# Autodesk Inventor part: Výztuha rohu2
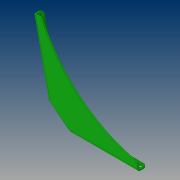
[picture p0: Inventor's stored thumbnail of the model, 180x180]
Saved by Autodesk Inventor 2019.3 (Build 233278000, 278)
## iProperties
Created: 2019-02
Part Number: Výztuha rohu2
Material: Ocel, měkká, svařovaná
Document SubType Name: Plech
Designer: B-hon
Density: 7.85 g/cm^3
Sheet Metal Rule: Výchozí_mm
Appearance: Tmavě zelená
Author: B-hon
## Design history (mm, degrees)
node "Plocha2"
  sketch "Náčrt1"
    geometry: L1 (0, 0)-(-10.396, 48.907); L2 (0, 0)-(50, 0); L3 (-51.978, 244.537)-(-37.306, 247.656); L4 (0, 0)-(226.092, 279.201); L5 (250, 0)-(250, 15); L6 (50, 0)-(50, -8); L7 (50, -8)-(250, -8); L8 (250, -8)-(250, 0); L9 (-10.396, 48.907)-(-18.221, 47.244); L10 (-18.221, 47.244)-(-59.803, 242.874); L11 (-59.803, 242.874)-(-51.978, 244.537); L12 (-51.978, 244.537)-(148.022, 244.537); A1 r 400 centre (329.584, 407.003) between (-37.306, 247.656) and (250, 15)
    constraints: 24 end point, 2 horizontal, 2 parallel, 2 point on circle, 1 centre point, 1 perpendicular, 1 point on line, 1 vertical
    dimensions: "d0" = 250 distance of L1.start L5.start; "d1" = 250 distance of L1.start L3.start; "d2" = 102 deg angle of L2 L1; "d3" = 15 distance of L3.start L3.end; "d5" = 51 deg angle of L2 L4 (= 0.5 x d2); "d6" = 400 radius of A1; "d39" = 200 distance of L7.end L6.end; "d40" = 8 distance of L2.end L6.end; "d41" = 200 distance of L1.end L3.start; "d43" = 8 distance of L1.end L9.end (= d40)
node "Obruba4"
node "Obruba5"
chamfer "Zkosení1" distance "d68" = 45; stored, may be unused: second distance "d69" = 2, angle "d70" = 45 deg
fillet "Zaoblení3" dims "d71" = 10
fillet "Zaoblení4" dims "d72" = 10
fillet "Zaoblení5" dims "d73" = 15
sketch "Náčrt9"
  geometry: A1 r 10 centre (190, 10) between (200, 10) and (190, 20) reference; A2 r 10 centre (10, 10) between (10, 20) and (0, 10) reference; 3 further points
  constraints: 2 coincident
hole "Díra1" sketch "Náčrt9" at (190, 10), (10, 10) diameter "d74" = 8.4; stored, may be unused: countersink angle "d78" = 90 deg, drill point angle "d80" = 118 deg; dims "d75" = 12, "d76" = 15.4, "d77" = 2, "d79" = 4 (= Tloušťka)
sketch "Náčrt10"
  geometry: A1 r 10 centre (10, -10) between (20, -10) and (10, 0) reference; A2 r 10 centre (10, -190) between (10, -200) and (20, -190) reference; 3 further points
  constraints: 2 coincident
hole "Díra2" sketch "Náčrt10" at (10, -10), (10, -190) diameter "d81" = 8.4; stored, may be unused: countersink angle "d85" = 90 deg, drill point angle "d87" = 118 deg; dims "d82" = 12, "d83" = 15.4, "d84" = 2, "d86" = 4 (= Tloušťka)
sketch "Náčrt11"
  geometry: L1 (190, 20)-(10, 20) reference; L2 (200, 0)-(200, 10) reference; 2 further points
  dimensions: "d88" = 10 distance from line of L1 point (140, 10); "d89" = 60 distance from line of L2 point (140, 10)
hole "Díra3" sketch "Náčrt11" at (140, 10) diameter "d90" = 8.4; stored, may be unused: countersink angle "d94" = 90 deg, drill point angle "d96" = 118 deg; dims "d91" = 12, "d92" = 15.4, "d93" = 2, "d95" = 4 (= Tloušťka)
sketch "Náčrt12"
  geometry: L1 (0, 0)-(10, 0) reference; L2 (20, -190)-(20, -10) reference; 2 further points
  dimensions: "d97" = 60 distance from line of L1 point (10, -60); "d98" = 10 distance from line of L2 point (10, -60)
hole "Díra4" sketch "Náčrt12" at (10, -60) diameter "d99" = 8.4; stored, may be unused: countersink angle "d103" = 90 deg, drill point angle "d105" = 118 deg; dims "d100" = 12, "d101" = 15.4, "d102" = 2, "d104" = 4 (= Tloušťka)
node "Těleso2"
feature "Deska5" dims "d44" = 4 (= Tloušťka)
sketch "Náčrt7"
  geometry: L1 through (100, 0) direction (-1, 0); L2 through (0, -14) direction (0, -1); L3 (0, -28)-(200, -28); L4 (200, -28)-(200, 0)
  constraints: 6 end point, 1 horizontal, 1 perpendicular, 1 vertical
feature "Deska6" dims "d44" = 4 (= Tloušťka), "d46" = 4 (= ŠířkaVýštipu), "d47" = 2 (= HloubkaVýštipu), "d48" = 8 (= MinimálníZbytek), "d49" = 4 (= PřechodovýPoloměr), "d50" = 28, "d51" = 90 deg, "d52" = 4 (= PoloměrOhybu), "d53" = 16 (= VelikostRohovéhoVýštipu), "d54" = 4 (= VelikostMezery), "d55" = 4 (= VelikostJacobihoPoloměru), "MezeraVystřižení" = 0.01
feature "Ohyb4" dims "d44" = 4 (= Tloušťka), "d46" = 4 (= ŠířkaVýštipu), "d47" = 2 (= HloubkaVýštipu), "d48" = 8 (= MinimálníZbytek), "d49" = 4 (= PřechodovýPoloměr), "d50" = 28, "d51" = 90 deg, "d52" = 4 (= PoloměrOhybu), "MezeraVystřižení" = 0.01
feature "Roh4" dims "d50" = 28, "d51" = 90 deg, "d53" = 16 (= VelikostRohovéhoVýštipu), "d54" = 4 (= VelikostMezery), "d55" = 4 (= VelikostJacobihoPoloměru)
sketch "Náčrt8"
  geometry: L1 through (100, 0) direction (-1, 2.47e-33); L2 through (0, -14) direction (0, -1); L3 (0, -28)-(200, -28); L4 (200, -28)-(200, 0)
  constraints: 6 end point, 1 horizontal, 1 perpendicular, 1 vertical
feature "Deska7" dims "d44" = 4 (= Tloušťka), "d56" = 4 (= ŠířkaVýštipu), "d57" = 2 (= HloubkaVýštipu), "d58" = 8 (= MinimálníZbytek), "d59" = 4 (= PřechodovýPoloměr), "d60" = 28, "d61" = 90 deg, "d62" = 4 (= PoloměrOhybu), "d63" = 16 (= VelikostRohovéhoVýštipu), "d64" = 4 (= VelikostMezery), "d65" = 4 (= VelikostJacobihoPoloměru), "MezeraVystřižení" = 0.01
feature "Ohyb5" dims "d44" = 4 (= Tloušťka), "d56" = 4 (= ŠířkaVýštipu), "d57" = 2 (= HloubkaVýštipu), "d58" = 8 (= MinimálníZbytek), "d59" = 4 (= PřechodovýPoloměr), "d60" = 28, "d61" = 90 deg, "d62" = 4 (= PoloměrOhybu), "MezeraVystřižení" = 0.01
feature "Roh5" dims "d60" = 28, "d61" = 90 deg, "d63" = 16 (= VelikostRohovéhoVýštipu), "d64" = 4 (= VelikostMezery), "d65" = 4 (= VelikostJacobihoPoloměru)
other parameters: "Tloušťka" = 4 (derived), "KSoučinitel" = 4.4, "PoloměrOhybu" = 4 (derived), "ŠířkaVýštipu" = 4 (= Tloušťka), "HloubkaVýštipu" = 2 (= 0.5 x Tloušťka), "VelikostRohovéhoVýštipu" = 16 (= 4 x Tloušťka), "MinimálníZbytek" = 8 (= 2 x Tloušťka), "PřechodovýPoloměr" = 4 (= PoloměrOhybu), "VelikostJacobihoPoloměru" = 4 (= PoloměrOhybu), "VelikostMezery" = 4 (= Tloušťka)
